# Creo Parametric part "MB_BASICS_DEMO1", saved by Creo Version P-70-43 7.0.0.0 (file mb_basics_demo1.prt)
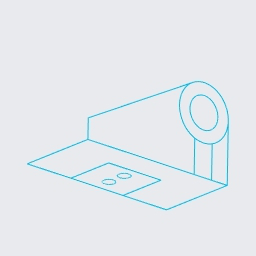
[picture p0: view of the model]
Units: millimeter Kilogram Sec (mmKs); MM, KILOGRAM, SECS

Created from: INLBS_PART_SOLID.PRT

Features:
  1. datum plane "RIGHT"
  2. datum plane "TOP"
  3. datum plane "FRONT"
  4. coordinate system
  5. sketch "Sketch 1"
  6. sketch "Sketch 2"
